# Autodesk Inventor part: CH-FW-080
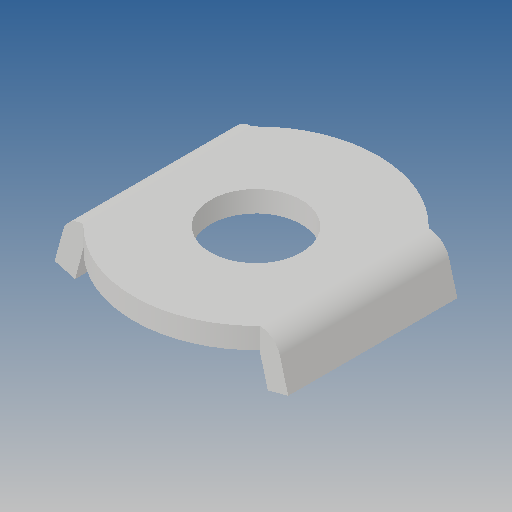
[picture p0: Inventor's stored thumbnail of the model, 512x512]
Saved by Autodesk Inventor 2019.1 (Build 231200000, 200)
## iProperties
Created: 2012-09
Part Number: CH-FW-080
Material: Ogólny
Document SubType Name: Modeling
Designer: CADENGINEERING4
Density: 1 g/cm^3
Appearance: Domyślna
Author: CADENGINEERING4
Revision Number: ÈÎºÎ
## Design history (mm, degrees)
feature "ÇÐ³ý-À­Éì6"
node "Bryła1"
